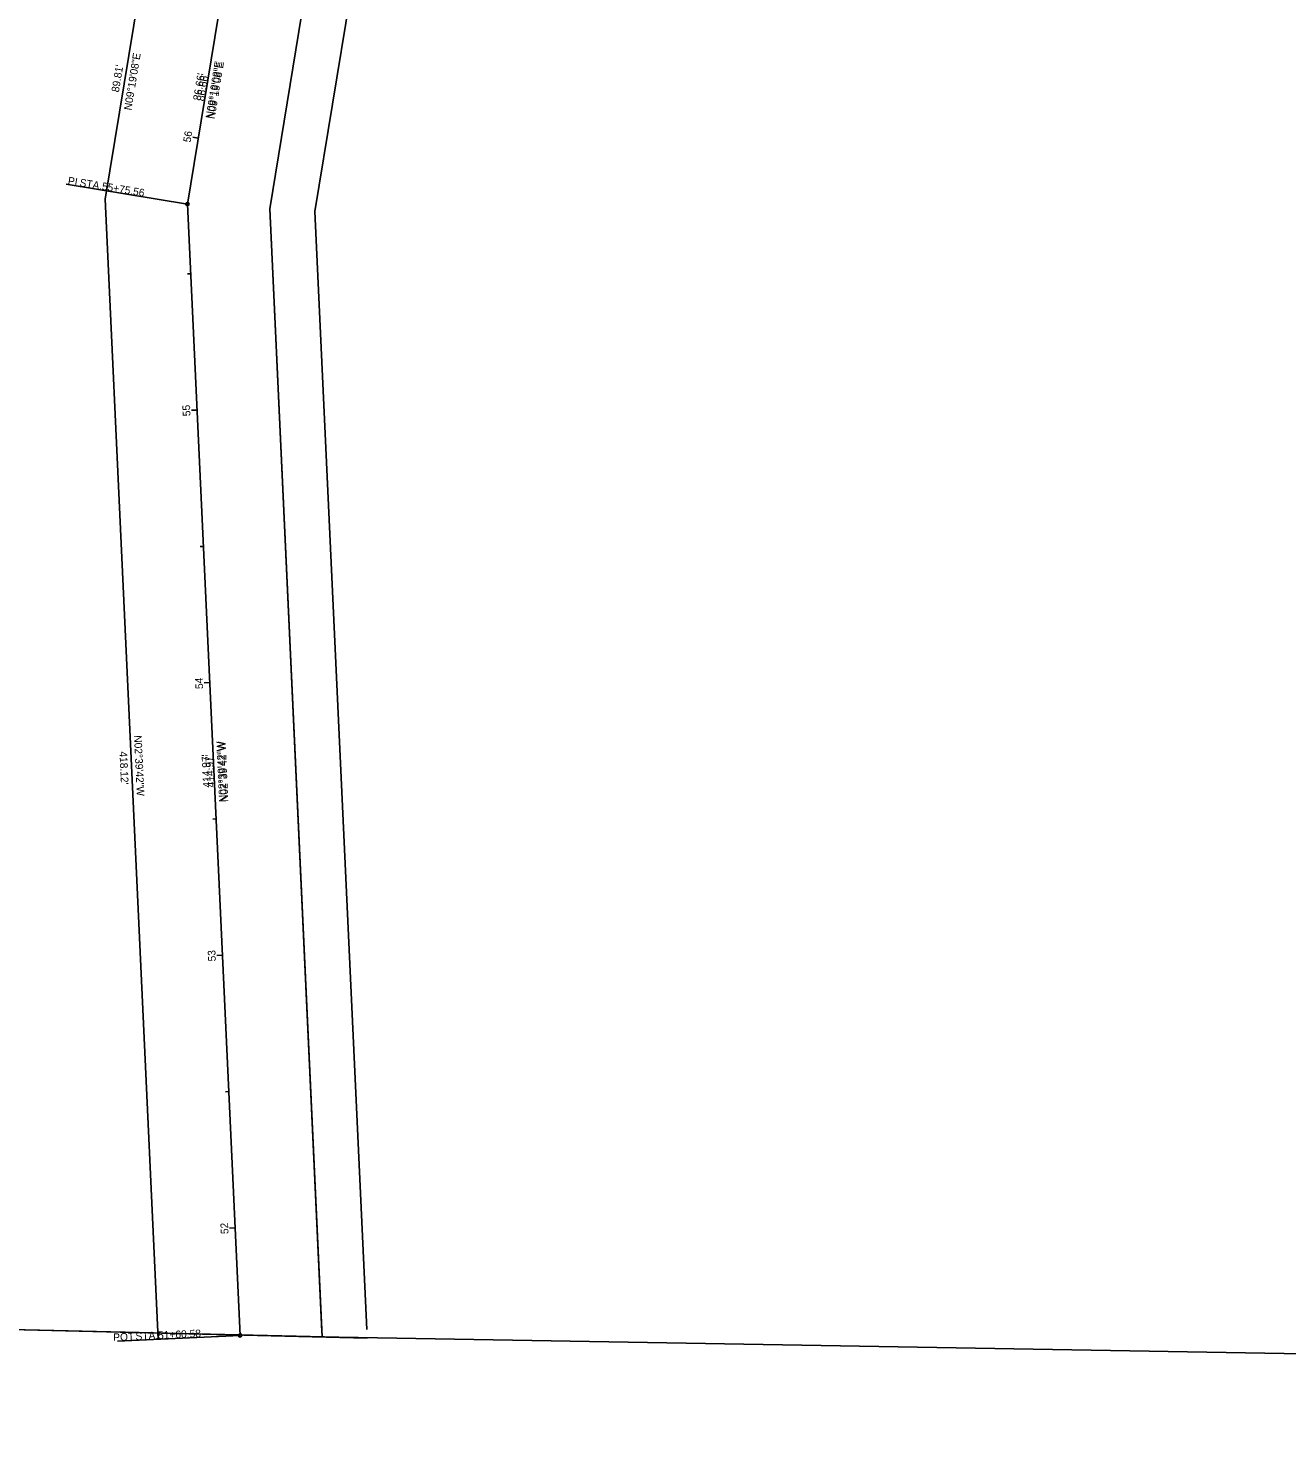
# Model space of a CAD drawing. Extents: x 2346746 to 2349554, y 247132 to 249252.
# Drawn here: x 2347228 to 2347689, y 247171 to 247688 of the extents above; entities that cross this region are included whole.
import ezdxf

# ---------------------------------------------------------------- set-up
doc = ezdxf.new("R2010")
doc.units = 0
for name, color, linetype in [('_CIVIL_CONSTRUCTION', 7, 'Continuous'), ('PF_X_Ground_Line', 7, 'Continuous'), ('UT_X_FO', 7, 'Continuous'), ('V-SURV-ANNO', 7, 'Continuous'), ('V-SURV-IPF', 7, 'Continuous'), ('V-TOPO-ANNO', 7, 'Continuous'), ('V-TOPO-BNDY', 7, 'Continuous'), ('V-TOPO-FEAT', 7, 'Continuous'), ('V-UTIL-WATR-LINE-ANNO', 7, 'Continuous'), ('V-UTIL-WATR-STRC', 7, 'Continuous')]:
    doc.layers.add(name, color=color, linetype=linetype)

msp = doc.modelspace()

# ---------------------------------------------------------------- linework, layer by layer
at = {"layer": '_CIVIL_CONSTRUCTION'}
for p, q in [((2347286.36, 247623.78), (2347241.96, 247631.07)), ((2347305.63, 247209.26), (2347260.68, 247207.17))]:
    msp.add_line(p, q, dxfattribs=at)
for centre in [(2347286.36, 247623.78), (2347305.63, 247209.26)]:
    msp.add_circle(centre, 0.6, dxfattribs=at)
at = {"layer": 'UT_X_FO'}
for p, q in [((2347286.36, 247623.78), (2347300.4, 247709.31)), ((2347305.63, 247209.26), (2347286.36, 247623.78))]:
    msp.add_line(p, q, dxfattribs=at)
at = {"layer": 'V-SURV-ANNO'}
for p, q in [((2347290.32, 247647.91), (2347288.35, 247648.23)), ((2347287.55, 247598.26), (2347286.35, 247598.2)), ((2347289.87, 247548.31), (2347287.87, 247548.22)), ((2347292.19, 247498.36), (2347290.99, 247498.31)), ((2347294.52, 247448.42), (2347292.52, 247448.32)), ((2347296.84, 247398.47), (2347295.64, 247398.42)), ((2347299.16, 247348.53), (2347297.16, 247348.43)), ((2347301.48, 247298.58), (2347300.28, 247298.52)), ((2347303.8, 247248.63), (2347301.81, 247248.54))]:
    msp.add_line(p, q, dxfattribs=at)
at = {"layer": 'V-TOPO-ANNO'}
for p, q in [((2347352.23, 247208.3), (2346746.15, 247222.96)), ((2347341.77, 247208.55), (2346832.55, 247220.87))]:
    msp.add_line(p, q, dxfattribs=at)
msp.add_lwpolyline([(2346864.44, 249252.04), (2347525.54, 249238.58), (2347621.59, 248667.77), (2348067.21, 248614.43), (2348211.26, 249235.08), (2349553.92, 249207.61), (2349518.11, 247171.02), (2347341.77, 247208.55)], dxfattribs=at)
at = {"layer": 'V-TOPO-BNDY'}
for p, q in [((2347256.25, 247625.54), (2347270.79, 247714.16)), ((2347316.48, 247622.03), (2347330, 247704.45)), ((2347316.48, 247622.03), (2347330, 247704.45)), ((2347275.67, 247207.87), (2347256.25, 247625.54)), ((2347335.6, 247210.65), (2347316.48, 247622.03)), ((2347335.69, 247208.7), (2347316.48, 247622.03))]:
    msp.add_line(p, q, dxfattribs=at)
at = {"layer": 'V-TOPO-FEAT'}
for p, q in [((2347333.04, 247621.07), (2347346.28, 247701.78)), ((2347333.04, 247621.07), (2347346.28, 247701.78)), ((2347352.08, 247211.42), (2347333.04, 247621.07)), ((2347352.08, 247211.42), (2347333.04, 247621.07))]:
    msp.add_line(p, q, dxfattribs=at)

# ---------------------------------------------------------------- texts
at = {"layer": '_CIVIL_CONSTRUCTION'}
for s, rotation, p in [('PI', 350.6811, (2347242.39, 247631.04)), (' STA. ', 350.6811, (2347245.67, 247630.5)), ('55+75.56', 350.6811, (2347254.87, 247628.99)), ('POT', 2.6618, (2347259.22, 247207.14)), (' STA. ', 2.6618, (2347266.34, 247207.47)), ('51+60.58', 2.6618, (2347275.65, 247207.9))]:
    msp.add_text(s, height=2.8, rotation=rotation, dxfattribs=at).set_placement(p)
at = {"layer": 'PF_X_Ground_Line'}
for s, rotation, p in [('N09°19\'08"E', 80.6811, (2347296.32, 247654.8)), ('N02°39\'42"W', 92.6618, (2347301.35, 247404.73))]:
    msp.add_text(s, height=2.8, rotation=rotation, dxfattribs=at).set_placement(p)
at = {"layer": 'V-SURV-ANNO'}
for s, rotation, p in [('56', 80.6811, (2347287.51, 247646.2)), ('55', 92.6618, (2347287.47, 247546.11)), ('54', 92.6618, (2347292.12, 247446.14)), ('53', 92.6618, (2347296.76, 247346.33)), ('52', 92.6618, (2347301.4, 247246.43))]:
    msp.add_text(s, height=2.8, rotation=rotation, dxfattribs=at).set_placement(p)
at = {"layer": 'V-SURV-IPF'}
for s, rotation, p in [("86.66'", 80.6811, (2347292.48, 247661.3)), ("414.97'", 92.6618, (2347296.26, 247410.09))]:
    msp.add_text(s, height=2.8, rotation=rotation, dxfattribs=at).set_placement(p)
at = {"layer": 'V-UTIL-WATR-LINE-ANNO'}
for s, rotation, p in [('N09°19\'08"E', 80.6811, (2347295.72, 247654.89)), ("86.66'", 80.6811, (2347291.14, 247661.52)), ('N02°39\'42"W', 92.6618, (2347300.75, 247404.7)), ("414.97'", 92.6618, (2347294.9, 247410.03))]:
    msp.add_text(s, height=2.8, rotation=rotation, dxfattribs=at).set_placement(p)
at = {"layer": 'V-UTIL-WATR-STRC'}
for s, rotation, p in [('N09°19\'08"E', 80.6811, (2347265.82, 247657.96)), ("89.81'", 80.6811, (2347261.24, 247664.59)), ('N02°39\'42"W', 272.6618, (2347266.78, 247429.07)), ("418.12'", 272.6618, (2347261.45, 247423.18))]:
    msp.add_text(s, height=2.8, rotation=rotation, dxfattribs=at).set_placement(p)

doc.saveas('drawing.dxf')
